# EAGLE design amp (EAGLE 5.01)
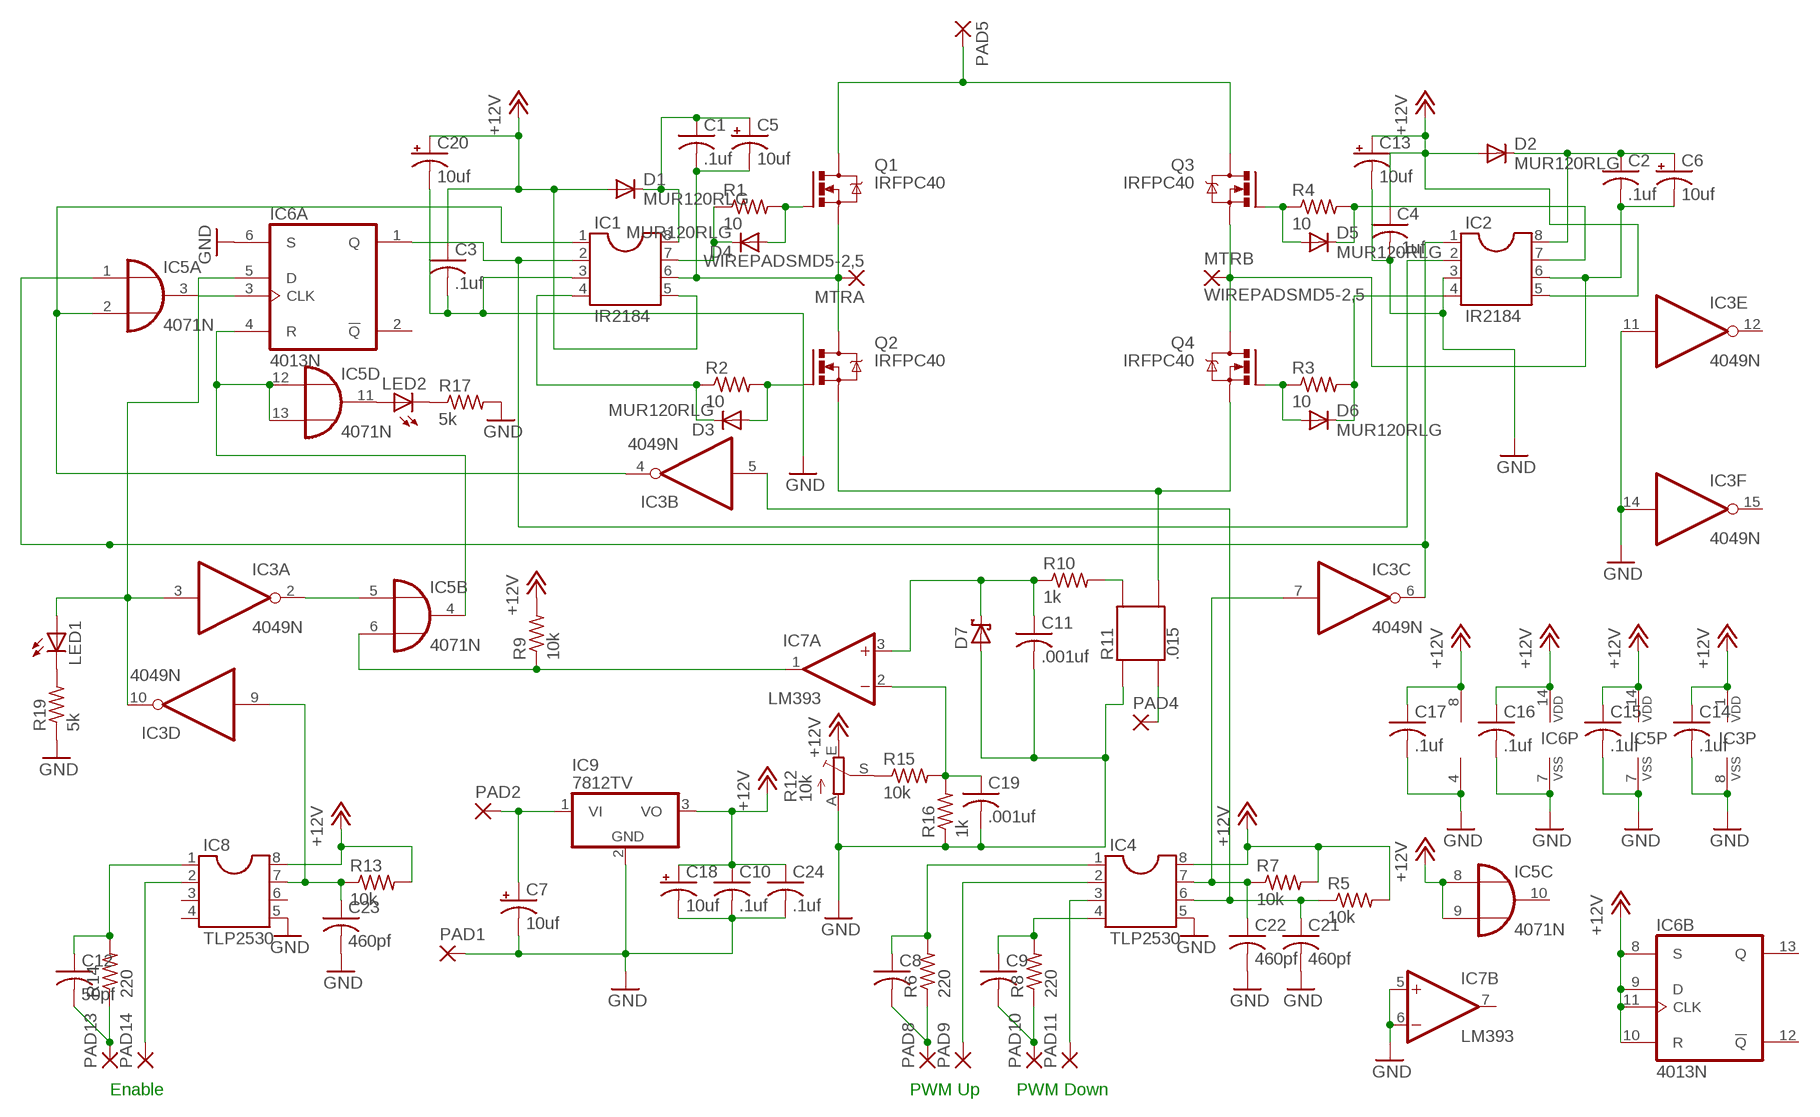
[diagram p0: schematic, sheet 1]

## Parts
C1  .1uf  C-US050-024X044  [C050-024X044]
C2  .1uf  C-US050-024X044  [C050-024X044]
C3  .1uf  C-US050-024X044  [C050-024X044]
C4  .1uf  C-US050-024X044  [C050-024X044]
C5  10uf  CPOL-USE2.5-5  [E2,5-5]
C6  10uf  CPOL-USE2.5-5  [E2,5-5]
C7  10uf  CPOL-USE2.5-5  [E2,5-5]
C8  C-US050-024X044  [C050-024X044]
C9  C-US050-024X044  [C050-024X044]
C10  .1uf  C-US050-024X044  [C050-024X044]
C11  .001uf  C-US050-024X044  [C050-024X044]
C12  50pf  C-US050-024X044  [C050-024X044]
C13  10uf  CPOL-USE2.5-5  [E2,5-5]
C14  .1uf  C-US050-024X044  [C050-024X044]
C15  .1uf  C-US050-024X044  [C050-024X044]
C16  .1uf  C-US050-024X044  [C050-024X044]
C17  .1uf  C-US050-024X044  [C050-024X044]
C18  10uf  CPOL-USE2.5-5  [E2,5-5]
C19  .001uf  C-US050-024X044  [C050-024X044]
C20  10uf  CPOL-USE2.5-5  [E2,5-5]
C21  460pf  C-US050-024X044  [C050-024X044]
C22  460pf  C-US050-024X044  [C050-024X044]
C23  460pf  C-US050-024X044  [C050-024X044]
C24  .1uf  C-US050-024X044  [C050-024X044]
D1  MUR120RLG  1N4933  [DO41-10]
D2  MUR120RLG  1N4933  [DO41-10]
D3  MUR120RLG  1N4933  [DO41-10]
D4  MUR120RLG  1N4933  [DO41-10]
D5  MUR120RLG  1N4933  [DO41-10]
D6  MUR120RLG  1N4933  [DO41-10]
D7  SCHOTTKY-DIODEDO35-7  [DO35-7]
IC1  IR2184  DIL8  [DIL08]
IC2  IR2184  DIL8  [DIL08]
IC3  4049N  [DIL16]
IC4  TLP2530  DIL8  [DIL08]
IC5  4071N  [DIL14]
IC6  4013N  [DIL14]
IC7  LM393  TL082P  [DIL08]
IC8  TLP2530  DIL8  [DIL08]
IC9  7812TV  [TO220V]
LED1  LED3MM  [LED3MM]
LED2  LED3MM  [LED3MM]
MTRA  WIREPADSMD5-2,5  [5-2,5]
MTRB  WIREPADSMD5-2,5  [5-2,5]
PAD1  WIREPAD2,54/1,0  [2,54/1,0]
PAD2  WIREPAD2,54/1,0  [2,54/1,0]
PAD4  WIREPAD4,16O1,6  [4,16O1,6]
PAD5  WIREPAD4,16O1,6  [4,16O1,6]
PAD8  WIREPAD2,54/1,0  [2,54/1,0]
PAD9  WIREPAD2,54/1,0  [2,54/1,0]
PAD10  WIREPAD2,54/1,0  [2,54/1,0]
PAD11  WIREPAD2,54/1,0  [2,54/1,0]
PAD13  WIREPAD2,54/1,0  [2,54/1,0]
PAD14  WIREPAD2,54/1,0  [2,54/1,0]
Q1  IRFPC40  [TO247BV]
Q2  IRFPC40  [TO247BV]
Q3  IRFPC40  [TO247BV]
Q4  IRFPC40  [TO247BV]
R1  10  R-US_0207/10  [0207/10]
R2  10  R-US_0207/10  [0207/10]
R3  10  R-US_0207/10  [0207/10]
R4  10  R-US_0207/10  [0207/10]
R5  10k  R-US_0207/10  [0207/10]
R6  220  R-US_0207/10  [0207/10]
R7  10k  R-US_0207/10  [0207/10]
R8  220  R-US_0207/10  [0207/10]
R9  10k  R-US_0207/10  [0207/10]
R10  1k  R-US_0207/10  [0207/10]
R11  .015  4LEG  [OHMLITE7W]
R12  10k  TRIM_EU-B64W  [B64W]
R13  10k  R-US_0207/10  [0207/10]
R14  220  R-US_0207/10  [0207/10]
R15  10k  R-US_0207/10  [0207/10]
R16  1k  R-US_0207/10  [0207/10]
R17  5k  R-US_0207/10  [0207/10]
R19  5k  R-US_0207/10  [0207/10]

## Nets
+12V: C3.1 C4.1 C10.1 C13.+ C14.1 C15.1 C16.1 C17.1 C18.+ C20.+ C24.1 D1.A D2.A IC1.5 IC2.5 IC3.1(P:VDD) IC4.8 IC5.8(C:I0) IC5.9(C:I1) IC5.14(P:VDD) IC6.8(B:S) IC6.9(B:D) IC6.10(B:R) IC6.11(B:CLK) IC6.14(P:VDD) IC7.8(P:V+) IC8.8 IC9.3(VO) R5.2 R7.2 R9.2 R12.E R13.2
GND: C3.2 C4.2 C7.- C10.2 C11.2 C13.- C14.2 C15.2 C16.2 C17.2 C18.- C19.2 C20.- C21.2 C22.2 C23.2 C24.2 D7.A IC1.3 IC2.3 IC3.8(P:VSS) IC3.11(E:I) IC3.14(F:I) IC4.5 IC5.7(P:VSS) IC6.6(A:S) IC6.7(P:VSS) IC7.4(P:V-) IC7.5(B:+IN) IC7.6(B:-IN) IC8.5 IC9.2(GND) PAD1.1(P) R11.2 R12.A R16.1 R17.2 R19.1
MTRA: C1.2 C5.- IC1.6 MTRA.1(P) Q1.S Q2.D
MTRB: C2.2 C6.- IC2.6 MTRB.1(P) Q3.S Q4.D
MTRPWR: PAD5.1(P) Q1.D Q3.D
N$1: IC4.3 PAD11.1(P)
N$2: IC4.2 PAD9.1(P)
N$3: C1.1 C5.+ D1.C IC1.8
N$4: C9.2 PAD10.1(P) R8.1
N$5: D4.A Q1.G R1.2
N$6: D3.A Q2.G R2.2
N$7: D6.A Q4.G R3.1
N$8: D5.A Q3.G R4.1
N$9: C23.1 IC3.9(D:I) IC8.7 R13.1
N$10: D4.C IC1.7 R1.1
N$11: D3.C IC1.4 R2.1
N$12: D6.C IC2.4 R3.2
N$14: IC2.1 IC3.6(C:O) IC5.1(A:I0)
N$15: C2.1 C6.+ D2.C IC2.8
N$16: C8.2 PAD8.1(P) R6.1
N$17: C7.+ IC9.1(VI) PAD2.1(P)
N$18: C22.1 IC3.7(C:I) IC4.7 R7.1
N$19: C21.1 IC3.5(B:I) IC4.6 R5.1
N$20: Q2.S Q4.S R11.3
N$21: C8.1 IC4.1 R6.2
N$22: C9.1 IC4.4 R8.2
N$23: IC1.2 IC2.2 IC6.1(A:Q)
N$24: IC5.3(A:O) IC6.3(A:CLK)
N$25: IC1.1 IC3.4(B:O) IC5.2(A:I1)
N$26: D5.C IC2.7 R4.2
N$27: IC5.6(B:I1) IC7.1(A:OUT) R9.1
N$28: R10.2 R11.1
N$29: IC5.11(D:O) LED2.A
N$30: IC3.3(A:I) IC3.10(D:O) IC6.5(A:D) LED1.A
N$31: IC3.2(A:O) IC5.5(B:I0)
N$32: IC8.2 PAD14.1(P)
N$33: R12.S R15.1
N$34: C12.2 PAD13.1(P) R14.1
N$35: C12.1 IC8.1 R14.2
N$36: C19.1 IC7.2(A:-IN) R15.2 R16.2
N$37: PAD4.1(P) R11.4
N$38: LED2.K(C) R17.1
N$39: C11.1 D7.C IC7.3(A:+IN) R10.1
N$40: IC5.4(B:O) IC5.12(D:I0) IC5.13(D:I1) IC6.4(A:R)
N$41: LED1.K(C) R19.2
Unconnected: IC3.12(E:O) IC3.15(F:O) IC5.10(C:O) IC6.2(A:!Q) IC6.12(B:!Q) IC6.13(B:Q) IC7.7(B:OUT) IC8.3 IC8.4 IC8.6

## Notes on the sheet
- Enable | PWM Up | PWM Down

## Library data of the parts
C1-C4 C8-C12 C14-C17 C19 C21-C24 = rcl:C-US: CAPACITOR, American symbol
C5-C7 C13 C18 C20 = rcl:CPOL-US: POLARIZED CAPACITOR, American symbol
D1-D6 = diode:1N4933: DIODE
D7 = diode:SCHOTTKY-DIODE: Schottky Diode
IC1 IC2 IC4 IC8 = ic-package:DIL8: Dual In Line / Socket
IC3 = 40xx:4049: Hex inverting BUFFER
IC5 = 40xx:4071: Quad 2-input OR
IC6 = 40xx:4013: Dual D FLIP FLOP, set/reset
IC7 = linear:TL082: OP AMP
IC9 = linear:78*: Positive VOLTAGE REGULATOR Source: http://cache.national.com/ds/LM/LM78L05.pdf http://www.fairchildsemi.com/ds/LM/LM7805.pdf
LED1 LED2 = led:LED: LED
MTRA MTRB PAD1 PAD2 PAD4 PAD5 PAD8-PAD11 PAD13 PAD14 = wirepad:WIREPAD: Wire PAD connect wire on PCB
Q1-Q4 = transistor-power:IRFPC40: N-CHANNEL MOS FET
R1 R17 = resistor:R-US_: RESISTOR, American symbol
R2-R10 R13-R16 R19 = rcl:R-US_: RESISTOR, American symbol
R11 = resistor-power:4LEG: ohmlite current sense resistor 10 series
R12 = pot:TRIM_EU-: POTENTIOMETER

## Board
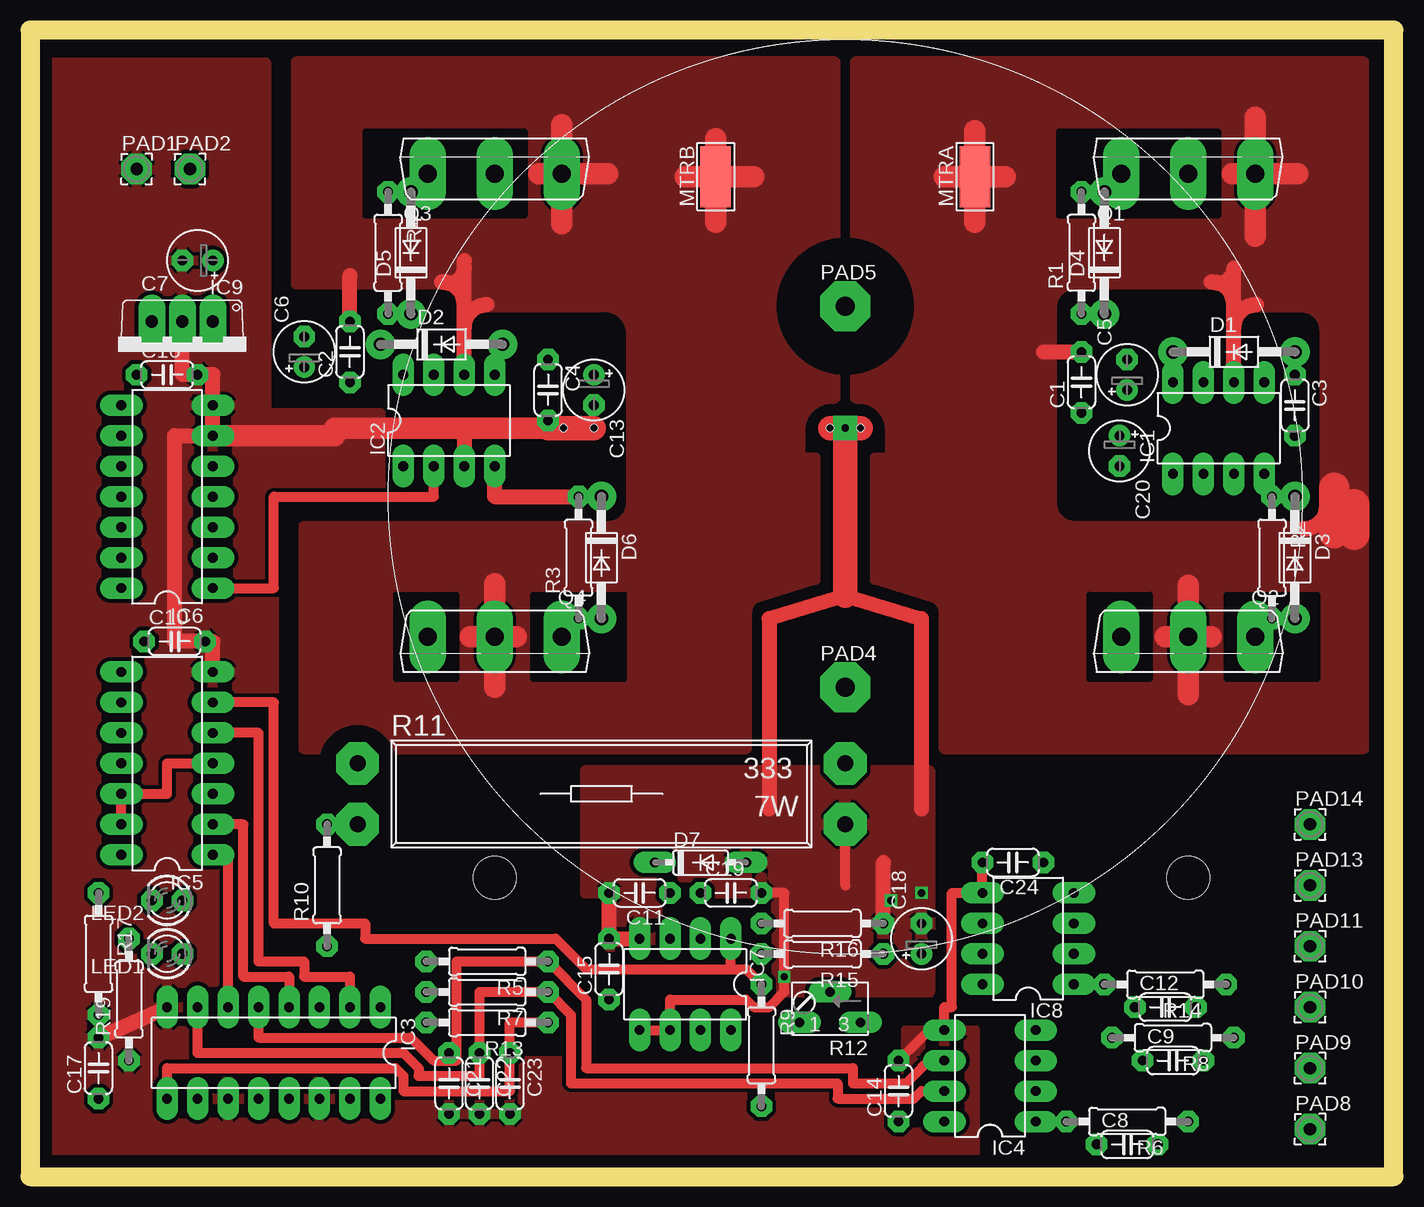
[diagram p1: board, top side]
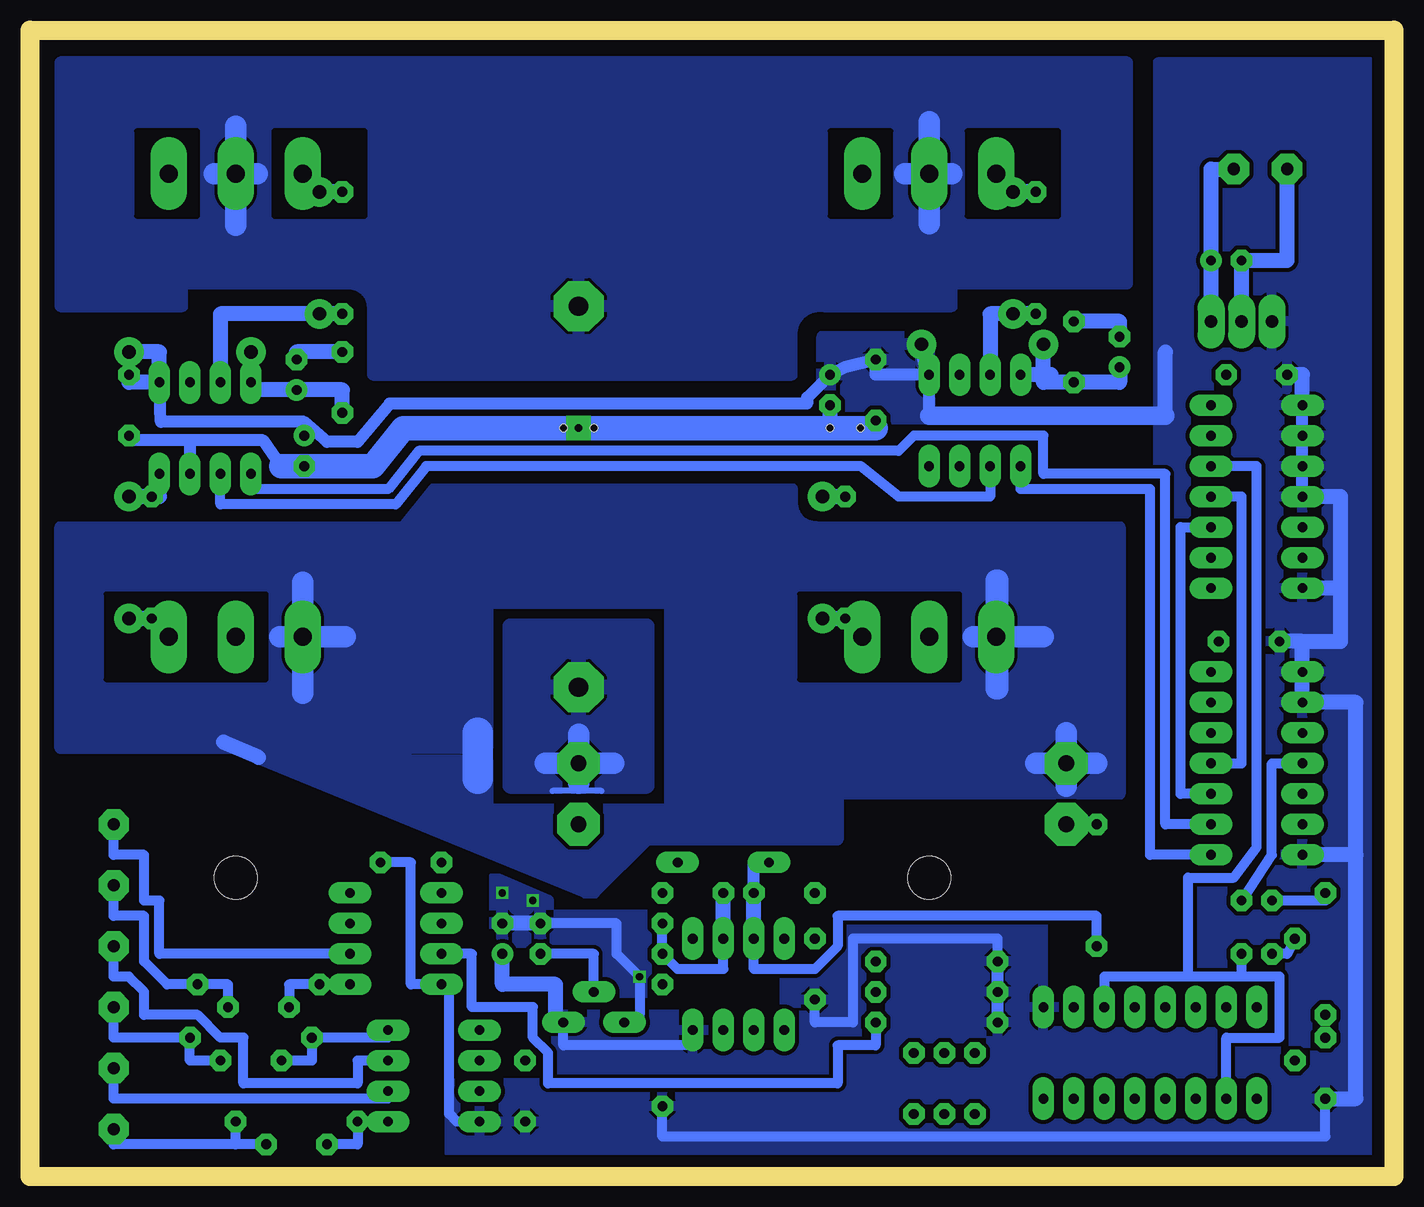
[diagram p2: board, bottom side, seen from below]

Size 113.65 x 95.56 mm. Coordinates in mm from the lower left corner, seen from the top.
Outline: 0,0 113.65,0 113.65,95.56 0,95.56 0,0
Copper layers (1*16): Top 0.035mm / dielectric 1.5mm / Bottom 0.035mm
Design rules "default *": minimum track width 10mil, minimum drill 24mil, track to track 13mil, track to pad 13mil, pad to pad 13mil, via to via 13mil, smd to smd 13mil, copper to edge 40mil, drill to drill 8mil, minimum pad ring 10mil, minimum via ring 8mil, stop-mask expansion 4mil, vias tented up to drill 0mil, thermal gap 10mil
Holes 3.56 mm at 38.73,24.92 96.51,24.92
Holes 0.6 mm at 44.44,62.38 46.98,62.38 69.21,62.38 66.67,62.38
tRestrict: area 66,70.6 to 69.8,74.4; area 30.5,41.4 to 35.6,48.5; area 94,80 to 99.1,87.1; area 88.3,41.4 to 93.3,48.5; area 41.9,41.4 to 49.5,48.5; area 27.9,80 to 35.6,87.1; area 85.7,80 to 93.3,87.1; area 99.7,41.4 to 107.3,48.5; area 25.4,32.5 to 29.2,36.3; area 36.2,80 to 41.3,87.1
bRestrict: area 94,41.4 to 99.1,48.5; area 99.7,80 to 104.8,87.1; area 41.9,80 to 47,87.1; area 36.2,41.4 to 41.3,48.5; area 41.9,41.4 to 49.5,48.5; area 27.9,80 to 35.6,87.1; area 85.7,80 to 93.3,87.1; area 99.7,41.4 to 107.3,48.5

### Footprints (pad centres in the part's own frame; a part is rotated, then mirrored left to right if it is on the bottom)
C050-024X044 = drill 0.813 octagon: 1 -2.54,0; 2 2.54,0
E2,5-5 = drill 0.813 pad 1.6 round: + -1.27,0 | drill 0.813 pad 1.6 octagon: - 1.27,0
DO41-10 = drill 1.118 round: A 5.08,0; C -5.08,0
DO35-7 = drill 0.813 long: A 3.81,0; C -3.81,0
DIL08 = drill 0.813 long: 1 -3.81,-3.81; 2 -1.27,-3.81; 3 1.27,-3.81; 4 3.81,-3.81; 5 3.81,3.81; 6 1.27,3.81; 7 -1.27,3.81; 8 -3.81,3.81
DIL16 = drill 0.813 long: 1 -8.89,-3.81; 2 -6.35,-3.81; 3 -3.81,-3.81; 4 -1.27,-3.81; 5 1.27,-3.81; 6 3.81,-3.81; 7 6.35,-3.81; 8 8.89,-3.81; 9 8.89,3.81; 10 6.35,3.81; 11 3.81,3.81; 12 1.27,3.81; 13 -1.27,3.81; 14 -3.81,3.81; 15 -6.35,3.81; 16 -8.89,3.81
DIL14 = drill 0.813 long: 1 -7.62,-3.81; 2 -5.08,-3.81; 3 -2.54,-3.81; 4 0,-3.81; 5 2.54,-3.81; 6 5.08,-3.81; 7 7.62,-3.81; 8 7.62,3.81; 9 5.08,3.81; 10 2.54,3.81; 11 0,3.81; 12 -2.54,3.81; 13 -5.08,3.81; 14 -7.62,3.81
TO220V = drill 1.016 long: 1 -2.54,-2.54; 2 0,-2.54; 3 2.54,-2.54
LED3MM = drill 0.813 octagon: A -1.27,0; K 1.27,0
5-2,5 = smd 2.54 x 5.08: 1 0,0
2,54/1,0 = drill 1.016 pad 2.54 octagon: 1 0,0
4,16O1,6 = drill 1.6 pad 4.166 octagon: 1 0,0
TO247BV = drill 1.499 long: D 0,-2.921; G -5.588,-2.921; S 5.588,-2.921
0207/10 = drill 0.813 octagon: 1 -5.08,0; 2 5.08,0
OHMLITE7W = drill 1.321 pad 3.556 octagon: 1 -20.32,-2.54; 2 20.32,-2.54; 3 -20.32,2.54; 4 20.32,2.54
B64W = drill 0.813 long: A 2.54,0; E -2.54,0; S 0,-2.54

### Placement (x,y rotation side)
C1  87.62,66.19 90 top
C2  26.66,68.73 90 top
C3  105.4,64.29 270 top
C4  43.17,65.56 270 top
C5  91.43,66.83 90 top
C6  22.85,68.73 90 top
C7  13.96,76.35 180 top
C8  91.43,2.69 0 top
C9  95.24,9.68 0 top
C10  12.06,44.6 0 top
C11  50.79,23.65 180 top
C12  94.61,14.12 0 top
C13  46.98,65.56 270 top
C14  72.38,7.14 90 top
C15  48.25,17.3 90 top
C16  11.42,66.83 0 top
C17  5.71,9.04 90 top
C18  74.29,19.84 90 top
C19  58.41,23.65 0 top
C20  90.8,60.48 270 top
C21  34.92,7.77 270 top
C22  37.46,7.77 270 top
C23  40,7.77 270 top
C24  81.91,26.19 180 top
D1  100.32,68.73 0 top
D2  34.28,69.37 0 top
D3  105.4,51.59 270 top
D4  89.53,76.99 90 top
D5  31.74,76.99 90 top
D6  47.62,51.59 270 top
D7  55.87,26.19 0 top
IC1  99.05,62.38 0 top
IC2  34.92,63.02 0 top
IC3  20.31,10.31 180 top
IC4  80,8.41 90 top
IC5  11.42,34.44 90 top
IC6  11.42,56.67 90 top
IC7  54.6,16.03 180 top
IC8  83.18,19.84 90 top
IC9  12.69,68.73 180 top
LED1  11.42,18.57 180 top
LED2  11.42,23.01 180 top
MTRA  78.73,83.34 0 top
MTRB  57.14,83.34 0 top
PAD1  8.88,83.97 0 top
PAD2  13.33,83.97 0 top
PAD4  67.94,40.79 0 top
PAD5  67.94,72.54 0 top
PAD8  106.67,3.96 0 top
PAD9  106.67,9.04 0 top
PAD10  106.67,14.12 0 top
PAD11  106.67,19.2 0 top
PAD13  106.67,24.28 0 top
PAD14  106.67,29.36 0 top
Q1  96.51,86.51 0 top
Q2  96.51,42.06 180 top
Q3  38.73,86.51 0 top
Q4  38.73,42.06 180 top
R1  87.62,76.99 90 top
R2  103.5,51.59 270 top
R3  45.71,51.59 90 top
R4  29.84,76.99 270 top
R5  38.09,17.93 180 top
R6  91.43,4.6 180 top
R7  38.09,15.39 180 top
R8  95.24,11.58 180 top
R9  60.95,10.95 270 top
R10  24.76,24.28 90 top
R11  47.62,31.9 0 top
R12  66.67,12.85 180 top
R13  38.09,12.85 180 top
R14  94.61,16.03 180 top
R15  66.03,18.57 180 top
R16  66.03,21.11 180 top
R17  5.71,18.57 270 top
R19  8.25,14.76 90 top

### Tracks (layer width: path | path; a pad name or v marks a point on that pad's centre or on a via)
+12V
  Bottom 0.813: R9.2 60.95,3.33 5.71,3.33 C17.1 | 69.84,13.49 R12.E 69.21,10.95 58.41,10.95 IC7.8 | C15.1 48.25,12.85 45.08,12.85 45.08,19.84 33.01,19.84 R5.2 | IC4.8 78.1,4.6 78.73,5.23 78.73,16.03 IC8.8 81.91,16.03 81.91,26.19 C24.1
  Bottom 1.016: 90.8,62.89 88.89,61.24 86.35,61.24 83.69,64.42 48.89,64.42 48.89,64.92 C13.+ 45.71,67.46 C4.1 43.17,66.83 IC2.5 38.73,63.4 | 90.8,62.89 102.74,62.89 IC1.5 | IC6.8 IC6.9 IC6.10 IC6.11 | 90.8,62.89 C20.+ | R13.2 R7.2 R5.2
  Bottom 1.27: D1.A 102.86,68.73 IC1.5 105.4,66.19 C3.1 | IC2.5 D2.A | 19.04,63.4 19.04,68.73 | C16.1 7.61,66.83 IC6.8 | IC6.11 4.44,56.67 4.44,49.05 | 4.44,49.05 IC6.14 | 7.61,44.6 IC5.8 IC5.9 3.17,39.52 3.17,26.82 | 7.61,44.6 C10.1 | 7.61,44.6 4.44,44.6 4.44,49.05 | 3.17,26.82 IC5.14 | C17.1 3.17,6.5 3.17,26.82 | C18.+ 74.29,16.03 69.84,16.03 69.84,13.49
  Bottom 1.524: 19.04,63.4 38.73,63.4
  pour Bottom: 47.62,63.15 47.62,70 38.73,70 38.73,63.15
  pour Bottom: 19.68,92.86 19.68,14.12 29.2,14.12 29.2,21.74 50.79,21.74 50.79,13.49 70.48,13.49 70.48,7.77 78.73,7.77 78.73,2.06 1.9,2.06 1.9,92.86
GND  (via drill 0.6, 0.6 pad 2.03)
  Top 0.406: 74.29,46.51 74.29,45.87
  Top 0.813: C14.2 74.92,12.22 IC4.5 76.19,14.12 76.83,14.12 76.83,23.65 IC8.5 C24.2 | IC7.6 IC7.5 IC7.6 | IC7.6 53.33,14.76 59.68,14.76 60.32,14.12 61.59,14.12 62.86,15.39 v62.86,16.66 62.86,23.65 C19.2 | 67.94,24.28 R11.2
  Top 1.27: 61.59,30.63 61.59,46.51 67.94,48.41 74.29,46.51 74.29,30.63 | 36.19,62.38 IC2.3 | 43.17,62.38 C4.2 | IC9.2 12.69,66.83 C16.2 15.23,66.83 IC6.7 IC6.6 12.06,61.75 12.06,44.6 C10.2 15.23,44.6 IC5.7 | C17.2 IC3.8 | R16.1 71.11,26.19 | IC7.4 C15.2 C11.2
  Top 1.778: 43.17,62.38 36.19,62.38 25.39,62.38 25.39,61.75 IC6.6
  Top 2.032: v67.94,62.38 67.94,48.41 | v67.94,62.38 69.21,62.38 | v67.94,62.38 66.67,62.38 | 43.17,62.38 46.98,62.38
  Bottom 0.813: 94.23,61.37 100.58,61.37 | 105.4,61.37 C3.2 | R12.A 62.86,13.49 v62.86,16.66 64.76,18.57 64.76,21.11 R16.1
  Bottom 1.016: 100.32,61.37 IC1.3 | 100.32,61.37 105.4,61.37 | C20.- 92.7,59.21 94.23,61.37 100.32,61.37
  Bottom 1.27: C4.2 43.17,62.38 46.98,62.38 C13.- | IC9.2 C7.- 8.88,76.35 PAD1.1 | R16.1 C18.-
  Bottom 2.032: 92.7,59.21 85.08,59.21 82.54,62.38 v67.94,62.38 43.17,62.38
  other vias: 74.29,23.65 71.75,23.01
  pour Top: 1.9,92.86 19.68,92.86 19.68,63.65 29.2,63.65 29.2,56.67 20.31,56.67 20.31,9.68 44.44,9.68 44.44,7.77 73.02,7.77 73.02,12.22 78.73,12.22 78.73,2.06 1.9,2.06
  pour Top: 46.35,33.81 74.92,33.81 74.92,15.39 62.22,15.39 62.22,23.65 52.7,23.65 52.7,19.2 48.25,19.2 48.25,23.65 46.35,23.65
  pour Bottom: 74.92,15.39 62.22,15.39 62.22,21.74 70.48,21.74 70.48,23.01 74.92,24.92
MTRA
  Top 1.27: IC1.6 100.32,70.77 | 100.32,70.77 100.32,72.67 | 100.32,72.67 100.32,75.72 arc-90 99.05,74.45 98.42,74.58 arc-90 100.32,72.67 | 84.45,68.73 C1.2 | 106.17,54 arc90 108.07,55.91 | 100.32,70.77 arc-90 102.23,72.67
  Top 1.778: Q2.D 98.42,44.98 | Q2.D 94.61,44.98 | Q2.D 96.51,49.3 | 96.51,40.16 Q2.D | Q1.S 100.2,83.59 | Q1.S 105.66,83.59 | Q1.S 102.1,88.29 | 102.1,78.39 Q1.S | MTRA.1 81.27,83.34 | MTRA.1 76.19,83.34 | MTRA.1 78.73,87.15 | 78.73,79.53 MTRA.1
  Top 2.54: 108.71,53.62 108.71,57.43 | 110.36,53.49 110.36,56.03
  Bottom 1.27: C1.2 91.43,68.73 C5.-
  pour Top: 68.83,92.86 68.83,64.92 arc-90 71.75,62.38 71.75,59.84 70.48,59.84 70.48,49.81 75.3,48.34 arc-73 76.19,47.12 76.19,35.71 111.12,35.71 111.12,54.13 87.08,54.13 arc-90 85.08,56.13 85.08,72.45 arc-90 87.08,74.45 100.96,74.45 100.96,72.54 105.94,72.54 arc-90 107.94,70.54 107.94,55.4 111.12,55.4 111.12,92.86
MTRB
  Top 1.27: IC2.6 36.19,70.77 | 36.19,70.77 36.19,72.67 | 36.19,72.67 36.19,75.72 | 36.19,75.72 36.19,76.35 | C2.2 26.66,75.08 | 36.19,72.67 arc90 34.28,74.58 34.92,74.45 arc90 36.19,75.72 | 36.19,70.77 arc-90 38.09,72.67
  Top 1.778: Q3.S 48.13,83.59 | Q3.S 44.32,79.4 | Q3.S 44.32,87.66 | 42.41,83.59 Q3.S | Q4.D 36.7,44.98 | Q4.D 40.51,44.98 | Q4.D 38.73,49.43 | 38.73,40.79 Q4.D | MTRB.1 60.32,83.34 | MTRB.1 54.6,83.34 | MTRB.1 57.14,86.51 | 57.14,79.53 MTRB.1
  Bottom 1.27: C2.2 22.85,71.27 C6.-
  pour Top: 22.22,92.86 22.22,74.45 36.82,74.45 36.82,72.54 47.52,72.54 arc-90 50.16,70.54 50.16,56.13 arc-90 48.16,54.13 22.85,54.13 22.85,35.71 59.68,35.71 59.68,47.12 arc-73 60.58,48.34 65.4,49.81 65.4,59.84 64.13,59.84 64.13,62.38 arc-90 67.05,64.92 67.05,92.86
MTRPWR
  Bottom 1.778: Q1.D 98.29,83.59 | Q1.D 94.74,83.59 | Q1.D 96.51,87.53 | 96.51,79.27 Q1.D | Q3.D 38.73,87.91 | Q3.D 40.76,83.59 | Q3.D 36.82,83.59 | 38.73,79.4 Q3.D
  pour Bottom: 22.22,92.86 111.12,92.86 111.12,72.54 100.96,72.54 100.96,74.45 87.08,74.45 arc90 85.08,72.45 85.08,66.83 50.16,66.83 50.16,70.54 arc90 47.52,72.54 36.82,72.54 36.82,74.45 22.22,74.45
N$1
  Bottom 0.813: IC4.3 86.35,9.68 86.35,7.77 95.88,7.77 95.88,11.58 97.78,11.58 99.69,13.49 104.13,13.49 104.13,15.39 105.4,16.66 106.67,16.66 PAD11.1
N$2
  Bottom 0.813: IC4.2 83.81,6.5 106.67,6.5 PAD9.1
N$3
  Bottom 1.016: 95.24,65.56 IC1.8
  Bottom 1.27: C1.1 87.62,65.56 C5.+ 95.24,65.56 | IC1.8 D1.C
N$4
  Bottom 0.813: PAD10.1 106.67,11.58 R8.1 100.32,9.68 C9.2
N$5
  Bottom 1.016: 90.8,83.59 Q1.G
  Bottom 1.27: R1.2 D4.A 90.8,82.07 90.8,83.59
N$6
  Bottom 1.016: Q2.G 102.23,44.98
  Bottom 1.27: D3.A R2.2 102.23,46.51 102.23,44.98
N$7
  Bottom 1.016: Q4.G 44.44,44.98
  Bottom 1.27: D6.A R3.1 44.44,46.51 44.44,44.98
N$8
  Bottom 0.813: 33.01,83.59 Q3.G
  Bottom 1.27: R4.1 D5.A 33.01,82.07 33.01,83.59
N$9
  Top 0.813: IC3.9 11.42,9.04 30.47,9.04 31.11,8.41 31.11,7.14 40,7.14 C23.1 40,12.85 R13.1
  Bottom 0.813: R13.1 43.17,10.95 46.35,10.95 46.35,7.77 70.48,7.77 70.48,10.31 71.75,11.58 71.75,14.12 76.83,14.12 76.83,18.57 IC8.7
N$10
  Bottom 1.27: IC1.7 97.78,71.91 D4.C | D4.C R1.1 D4.C
N$11
  Bottom 1.27: IC1.4 102.86,56.67 R2.1 D3.C
N$12
  Top 1.27: IC2.4 38.73,56.67 R3.2
  Bottom 1.27: R3.2 D6.C
N$14
  Top 0.813: IC3.6 16.5,26.82 IC5.1
  Bottom 0.813: IC2.1 31.11,57.3 20.31,57.3 20.31,26.82 IC5.1
N$15
  Bottom 1.27: 29.2,66.19 C2.1 22.85,66.19 C6.+ | 29.2,66.19 28.57,66.83 IC2.8 | 29.2,66.19 D2.C
N$16
  Bottom 0.813: PAD8.1 106.67,2.69 96.51,2.69 | C8.2 96.51,2.69 | 96.51,2.69 R6.1
N$17
  Bottom 1.27: IC9.1 C7.+ 15.23,83.97 PAD2.1
N$18
  Top 0.813: IC3.7 13.96,10.31 31.11,10.31 32.38,9.04 32.38,8.41 37.46,8.41 C22.1 37.46,15.39 R7.1 45.08,13.49 45.08,7.77 67.3,7.77 67.3,6.5 72.38,6.5 73.65,6.5 74.29,7.14 IC4.7
N$19
  Top 0.813: IC3.5 19.04,11.58 31.74,11.58 33.65,9.68 35.55,9.68 | 35.55,9.68 C21.1 | 35.55,9.68 35.55,17.93 R5.1 46.35,14.76 46.35,9.04 68.57,9.04 68.57,7.77 73.02,7.77 74.29,9.04 74.92,9.68 IC4.6
N$20
  Bottom 1.27: 94.61,34.95 97.53,36.22
  Bottom 1.778: Q2.S 92.83,44.98 | Q2.S 87.37,44.98 | Q2.S 90.93,49.56 | 90.93,40.29 Q2.S | Q4.S 29.2,44.98 | Q4.S 33.14,49.68 33.01,49.68 33.01,40.67 33.14,40.67 Q4.S | Q4.S 35.05,44.98 | R11.3 29.84,34.44 | R11.3 24.76,34.44 | R11.3 27.3,36.98 | 27.3,32.54 R11.3
  Bottom 2.54: 76.32,33.17 76.32,36.98
  pour Bottom: 22.85,54.13 22.85,31.9 46.35,31.9 46.35,28.09 62.22,28.09 66.67,23.65 67.3,23.65 94.61,34.82 75.56,34.7 75.56,30.63 60.32,30.63 60.32,47.78 75.56,47.78 75.56,35.71 111.12,35.71 111.12,54.13 82.54,54.13 80,57.3 50.16,57.3 50.16,56.13 arc-90 48.16,54.13
N$21
  Bottom 0.813: IC4.1 R6.2 86.35,2.69 C8.1
N$22
  Bottom 0.813: IC4.4 83.81,11.58 R8.2 90.16,9.68 C9.1
N$23
  Top 0.813: IC6.1 20.31,49.05 20.31,56.67 33.65,56.67 IC2.2
  Bottom 0.813: IC1.2 97.78,56.03 83.18,56.03 80.64,59.21 44.44,59.21 41.27,56.67 33.65,56.67 IC2.2
N$24
  Bottom 0.813: IC5.3 17.77,31.9 17.77,54.13 IC6.3
N$25
  Top 0.813: IC5.2 17.77,29.36 17.77,16.66 21.58,16.66 IC3.4
  Bottom 0.813: IC1.1 95.24,57.3 83.81,57.3 81.27,60.48 41.27,60.48 40,61.75 29.2,61.75 29.2,58.57 19.04,58.57 19.04,29.36 IC5.2
N$26
  Bottom 1.27: IC2.7 33.65,71.91 D5.C R4.2
N$27
  Top 0.813: IC5.6 20.31,39.52 20.31,21.11 27.93,21.11 27.93,19.84 43.81,19.84 46.35,17.3 58.41,17.3 | 58.41,17.3 IC7.1 | 58.41,17.3 59.68,17.3 R9.1
N$28
  Bottom 1.27: R10.2 R11.1
N$29
  Bottom 0.813: IC5.11 10.15,34.44 10.15,26.82 LED2.A
N$30
  Bottom 0.813: IC6.5 11.42,59.21 11.42,27.46 13.33,24.92 17.14,24.92 17.14,16.66 | 12.69,16.66 9.52,16.66 9.52,11.58 13.96,11.58 IC3.10 | 12.69,16.66 17.14,16.66 | 17.14,16.66 24.12,16.66 IC3.3 | 12.69,16.66 LED1.A
N$31
  Top 0.813: IC5.5 19.04,36.98 19.04,17.93 22.85,17.93 22.85,16.66 26.66,16.66 IC3.2
N$32
  Bottom 0.813: IC8.2 102.86,18.57 102.86,23.01 104.13,23.01 104.13,26.82 106.67,26.82 PAD14.1
N$33
  Bottom 0.813: R12.S 66.67,18.57 R15.1
N$34
  Bottom 0.813: C12.2 97.15,16.03 R14.1 102.23,16.03 104.13,17.93 104.13,21.74 106.67,21.74 PAD13.1
N$35
  Bottom 0.813: IC8.1 R14.2 92.07,16.03 C12.1
N$36
  Bottom 0.813: IC7.2 55.87,17.3 59.68,17.3 R15.2 R16.2
  Bottom 1.27: IC7.2 C19.1
N$37
  Bottom 0.254: 67.94,32.16 67.94,32.79
  Bottom 0.508: 66.03,32.16 67.94,32.16 70.1,32.16
  Bottom 1.778: R11.4 70.73,34.44 | R11.4 65.02,34.44 | R11.4 67.94,36.86 | 67.94,32.79 R11.4
  pour Bottom: 62.22,45.87 73.65,45.87 73.65,32.54 62.22,32.54
N$38
  Bottom 0.813: LED2.K 5.71,23.01 R17.1
N$39
  Bottom 0.813: R10.1 24.76,21.74 46.35,21.74 46.35,19.2 48.25,17.3 53.33,17.3 IC7.3
  Bottom 1.016: C11.1 53.33,26.19 D7.C
  Bottom 1.27: IC7.3 C11.1
N$40
  Top 0.813: IC5.13 IC5.12 11.42,31.9 11.42,34.44 IC5.4
  Bottom 0.813: IC6.4 12.69,56.67 12.69,34.44 IC5.4
N$41
  Bottom 0.813: LED1.K 8.88,18.57 R19.2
